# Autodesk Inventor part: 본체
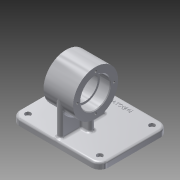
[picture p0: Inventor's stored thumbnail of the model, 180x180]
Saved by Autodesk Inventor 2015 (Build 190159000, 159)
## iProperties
Created: 2019-09
Part Number: 본체
Material: 알루미늄 6061
Document SubType Name: Modeling
Designer: now
Density: 2.7 g/cm^3
Appearance: 알루미늄 - 평지
Mass: 552.22 g
Surface Area: 493.79 cm^2
Volume: 204.526 cm^3
Author: now
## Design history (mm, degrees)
sketch "스케치1"
  geometry: L1 (-63, 49)-(63, 49); L2 (63, 49)-(63, -49); L3 (63, -49)-(-63, -49); L4 (-63, -49)-(-63, 49); 3 further points
  constraints: 8 end point, 2 midpoint, 2 parallel, 1 horizontal, 1 horizontal alignment, 1 perpendicular, 1 vertical alignment
  dimensions: "d0" = 126 distance of L2.end L3.end; "d1" = 98 distance of L3.end L1.start
extrude "돌출1" new body sketch "스케치1" distance "d2" = 9; taper "d3" = 0 deg
fillet "모깎기1" dims "d4" = 12
sketch "스케치2"
  geometry: A1 r 12 centre (-51, 37) between (-51, 49) and (-63, 37) reference; A2 r 12 centre (-51, -37) between (-63, -37) and (-51, -49) reference; A3 r 12 centre (51, -37) between (51, -49) and (63, -37) reference; A4 r 12 centre (51, 37) between (63, 37) and (51, 49) reference; 1 further point
hole "구멍1" sketch "스케치2" at (-51, -37), (51, -37), (51, 37), (-51, 37) diameter "d5" = 4.5; stored, may be unused: countersink angle "d9" = 90 deg, drill point angle "d11" = 118 deg; dims "d6" = 6, "d7" = 8, "d8" = 4.4, "d10" = 8
sketch "스케치15"
  geometry: L1 (37, 0)-(-37, 0) reference; C1 r 32 at (-13, 59); 2 further points
  constraints: 1 centre point
  dimensions: "d56" = 64 diameter of C1; "d70" = 36 horizontal distance of point (-49, 9) C1.centre; "d128" = 59 distance from line of L1 C1.centre
extrude "돌출8" join sketch "스케치15" stored distance "d57" = 42; taper "d58" = 0 deg
sketch "스케치18"
  geometry: L1 (63, -37)-(63, 37) reference; L2 (51, 49)-(-51, 49) reference; L3 (-4, 19)-(4, 19); L4 (4, 19)-(4, -45); L5 (4, -45)-(-4, -45); L6 (-4, -45)-(-4, 19); L7 (-4, 19)-(4, -45); L8 (4, 19)-(-4, -45); L9 (63, 37)-(63, -37) reference; L10 (51, -49)-(-51, -49) reference; L11 (-63, -37)-(-63, 37) reference; L12 (-51, 49)-(51, 49) reference; L13 (17, -9)-(-17, -9); L14 (-17, -9)-(-17, -17); L15 (-17, -17)-(17, -17); L16 (17, -17)-(17, -9); L17 (17, -9)-(-17, -17); L18 (-17, -9)-(17, -17); C1 r 4 at (51, 37) reference; C2 r 4 at (-51, -37) reference; C3 r 4 at (51, -37) reference; C4 r 4 at (-51, 37) reference; A1 r 12 centre (51, 37) between (63, 37) and (51, 49) reference; A2 r 12 centre (51, -37) between (51, -49) and (63, -37) reference; A3 r 12 centre (-51, -37) between (-63, -37) and (-51, -49) reference; A4 r 12 centre (-51, 37) between (-51, 49) and (-63, 37) reference; 5 further points
  constraints: 24 end point, 6 midpoint, 4 parallel, 2 horizontal, 2 perpendicular, 1 coincident
  dimensions: "d74" = 8 distance between parallel lines of L6 L4; "d75" = 36 distance from line of L10 point (0, -13); "d76" = 64 distance between parallel lines of L3 L5; "d77" = 8 distance between parallel lines of L15 L13; "d78" = 34 distance between parallel lines of L14 L16; "d79" = 63 distance from line of L1 point (0, -13); "d80" = 62 distance from line of point (0, -13) L2 (derived)
extrude "돌출11" join sketch "스케치18" distance "d81" = 50; taper "d82" = 0 deg
fillet "모깎기2" dims "d83" = 4
fillet "모깎기3" dims "d84" = 4
sketch "스케치19"
  geometry: C1 r 32 at (0, 0) reference; C2 r 21 at (0, 0); 1 further point
  constraints: 1 centre point, 1 coincident
  dimensions: "d85" = 42 diameter of C2
extrude "돌출12" cut sketch "스케치19" distance "d86" = 15; taper "d87" = 0 deg
sketch "스케치20"
  geometry: C1 r 21 at (0, 0) reference; C2 r 18 at (0, 0); 1 further point
  constraints: 1 centre point, 1 coincident
  dimensions: "d88" = 36 diameter of C2
extrude "돌출13" cut sketch "스케치20" distance "d89" = 12; taper "d90" = 0 deg
sketch "스케치21"
  geometry: C1 r 18 at (0, 0) reference; C2 r 21 at (0, 0); 1 further point
  constraints: 1 centre point, 1 coincident
  dimensions: "d91" = 42 diameter of C2
extrude "돌출14" cut sketch "스케치21" distance "d92" = 15; taper "d93" = 0 deg
sketch "스케치22"
  geometry: C1 r 21 at (0, 0) reference; 2 further points
  constraints: 1 horizontal alignment
  dimensions: "d94" = 26 distance of C1.centre point (26, 0)
hole "구멍2" sketch "스케치22" at (26, 0) diameter "d95" = 3.242; stored, may be unused: countersink angle "d99" = 90 deg, drill point angle "d101" = 118 deg; dims "d96" = 8, "d97" = 4, "d98" = 2, "d100" = 10
sketch "스케치23"
  geometry: C1 r 21 at (0, 0) reference; 2 further points
  constraints: 1 horizontal alignment
  dimensions: "d105" = 26 distance of C1.centre point (-26, 0)
hole "구멍3" sketch "스케치23" at (-26, 0) diameter "d106" = 3.242; stored, may be unused: countersink angle "d110" = 90 deg, drill point angle "d112" = 118 deg; dims "d107" = 8, "d108" = 4, "d109" = 2, "d111" = 10
sketch "스케치24"
  geometry: L1 (51, 49)-(-51, 49) reference; 3 further points
  constraints: 1 other
  dimensions: "d116" = 10 distance from line of point (0, 39) L1; "d117" = 63 horizontal distance of point (63, 37) point (0, 39)
feature "엠보싱1" sketch "스케치24" dims "d0" = 126, "d1" = 98, "d10" = 8, "d118" = 0.5, "d119" = 0
fillet "모깎기4" dims "d120" = 0.3, "d121" = 0.3
chamfer "모따기1" distance "d122" = 1; stored, may be unused: second distance "d123" = 2, angle "d124" = 45 deg
fillet "모깎기5" dims "d125" = 3
fillet "모깎기6" dims "d126" = 3
fillet "모깎기7" dims "d127" = 3
node "솔리드1"
pattern_circular "원형 패턴1" dims angle "d103" = 360 deg
pattern_circular "원형 패턴2" dims angle "d114" = 360 deg
node "절단 모서리 투영3"
